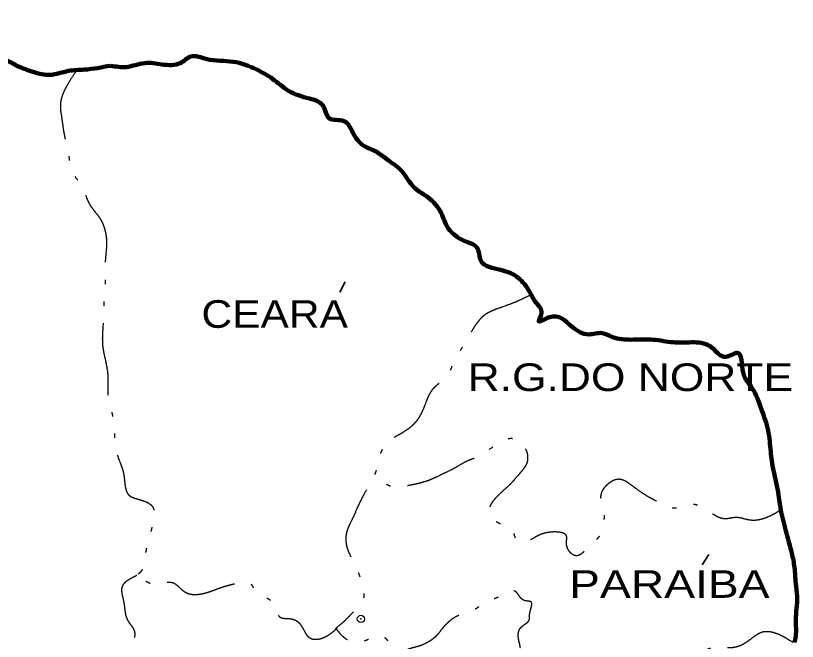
# Model space of a CAD drawing. Extents: x 512883 to 1063249, y 8784064 to 9081064.
# Drawn here: x 1001709 to 1034045, y 8999558 to 9025452 of the extents above; entities that cross this region are included whole.
import ezdxf

# ---------------------------------------------------------------- set-up
doc = ezdxf.new("R2010")
doc.units = 0
doc.header["$LTSCALE"] = 600
doc.header["$PDMODE"] = 32
doc.header["$PDSIZE"] = 300
doc.linetypes.add('DASH_DOUBLE_DOT', pattern=[9.2, 5, -1.2, 0.3, -1.2, 0.3, -1.2])
doc.layers.add('1', color=7, linetype='Continuous', lineweight=25)

msp = doc.modelspace()

# ---------------------------------------------------------------- linework, layer by layer
at = {"layer": '1', "lineweight": 35}
for p, q in [((1015118.6, 9014005.3), (1015336.7, 9014441.3)), ((1030108.9, 9002721.7), (1030381.5, 9003157.7))]:
    msp.add_line(p, q, dxfattribs=at)
at = {"layer": '1', "lineweight": 140}
for points in [[(996367.1, 9025452.4), (996476.1, 9025343.4), (997184.8, 9025234.4), (997784.4, 9024961.8), (998275, 9024852.8), (998056.9, 9024253.2), (998602, 9024144.2), (999365.2, 9023926.1), (1000400.9, 9023817.1), (1001218.5, 9023653.6), (1001763.6, 9023381), (1002472.3, 9023108.5), (1003126.4, 9022999.5), (1003889.5, 9023163), (1004543.7, 9023217.5), (1005633.9, 9023381)], [(1005633.9, 9023381), (1006288, 9023326.5), (1007051.1, 9023490), (1007759.8, 9023435.5), (1008522.9, 9023490), (1008959, 9023762.6), (1009613.1, 9023653.6), (1010703.3, 9023544.6), (1011684.5, 9023217.5), (1012338.6, 9022835.9), (1012992.7, 9022345.3), (1013864.9, 9022018.3), (1014410, 9021745.7), (1014682.6, 9021200.6), (1015282.2, 9021091.6), (1015663.7, 9020601), (1016045.3, 9020110.4), (1016590.4, 9019837.8), (1017135.5, 9019456.3), (1017626.1, 9019074.7), (1018225.7, 9018311.6), (1018770.8, 9017930), (1019315.9, 9017275.9), (1019588.5, 9016676.3), (1019970, 9016294.7), (1020406.1, 9016076.7), (1020787.7, 9015858.6), (1020951.2, 9015313.5), (1021768.9, 9014931.9), (1022423, 9014659.4), (1022913.6, 9014114.3), (1023240.7, 9013569.2), (1023458.7, 9013133.1), (1023349.7, 9012806), (1023785.8, 9012969.6), (1024712.4, 9012588), (1025421.1, 9012260.9), (1025966.2, 9012315.5), (1026402.2, 9012151.9), (1027165.4, 9012042.9), (1028092.1, 9012042.9), (1028909.7, 9011933.9), (1029672.8, 9011933.9), (1030436, 9011770.3), (1031090.1, 9011334.3), (1031580.7, 9011497.8), (1031798.8, 9010680.1), (1032180.3, 9010026), (1032561.9, 9009153.9), (1032834.4, 9008281.7), (1032943.5, 9007409.5), (1033052.5, 9006646.4), (1033270.5, 9005610.7), (1033379.5, 9004902.1), (1033597.6, 9004029.9), (1033815.6, 9003212.2), (1033924.6, 9002612.6), (1033979.2, 9001958.5), (1034033.7, 9001413.4), (1033979.2, 9000432.2), (1033979.2, 8999778.1), (1033924.6, 8999505.6)]]:
    msp.add_spline(points, degree=3, dxfattribs=at)
at = {"layer": '1', "linetype": 'DASH_DOUBLE_DOT'}
for points in [[(1004216.6, 9023163), (1003835, 9022563.4), (1003562.5, 9021800.2), (1003617, 9021200.6), (1003726, 9020492), (1003889.5, 9019783.3), (1004053.1, 9018965.7), (1004434.6, 9018420.6), (1004761.7, 9017657.5), (1005197.8, 9017057.8), (1005470.3, 9016076.7), (1005415.8, 9015259), (1005415.8, 9014441.3), (1005361.3, 9013841.7), (1005361.3, 9013242.1), (1005306.8, 9011824.9), (1005524.8, 9010516.6), (1005524.8, 9009753.5), (1005742.9, 9008772.3), (1005797.4, 9008063.7), (1005906.4, 9007300.5), (1006179, 9006482.9), (1006397, 9005610.7), (1006942.1, 9005392.7), (1007378.2, 9005120.1), (1007378.2, 9004411.5), (1007214.7, 9003757.3), (1007051.1, 9003048.7), (1006887.6, 9002449.1), (1006778.6, 9002340.1)], [(1023022.6, 9013896.2), (1022314, 9013569.2), (1021714.4, 9013351.1), (1021060.2, 9013024.1), (1020624.2, 9012479), (1020242.6, 9011824.9), (1019861, 9011170.7), (1019479.4, 9010462.1), (1018988.8, 9010026), (1018607.3, 9009262.9), (1018280.2, 9008663.3), (1017680.6, 9008172.7), (1017026.5, 9007736.6), (1016699.4, 9006973.5), (1016590.4, 9006537.4), (1016317.8, 9005992.3), (1015881.8, 9005174.6), (1015663.7, 9004684), (1015391.2, 9004029.9), (1015391.2, 9003539.3), (1015718.2, 9002776.2), (1016045.3, 9001904), (1016099.8, 9001358.9), (1015609.2, 9000704.8), (1015227.7, 9000323.2), (1014955.1, 9000105.2)], [(1033379.5, 9005011.1), (1032779.9, 9004684), (1032071.3, 9004575), (1031526.2, 9004684), (1031035.6, 9004629.5), (1030436, 9004902.1), (1029618.3, 9005229.1), (1028964.2, 9005065.6), (1028473.6, 9005229.1), (1027765, 9005610.7), (1027219.9, 9005992.3), (1026674.8, 9006264.8), (1026184.2, 9006046.8), (1025911.7, 9005610.7), (1026020.7, 9005011.1), (1026020.7, 9004411.5), (1025857.1, 9003920.9), (1025475.6, 9003539.3), (1024876, 9003103.2), (1024494.4, 9003593.8), (1024494.4, 9003920.9), (1023949.3, 9004084.4), (1023295.2, 9003920.9), (1022859.1, 9003702.8), (1022477.5, 9003702.8), (1022259.5, 9004138.9), (1022041.4, 9004302.5), (1021659.8, 9004466), (1021332.8, 9004847.6), (1022205, 9006101.3), (1022586.5, 9006537.4), (1022859.1, 9006918.9), (1022859.1, 9007409.5), (1022641, 9007736.6), (1022423, 9007900.1), (1021005.7, 9007300.5), (1020678.7, 9007137), (1020406.1, 9007028), (1019915.5, 9006755.4), (1019261.4, 9006428.3), (1018770.8, 9006210.3), (1017898.7, 9005992.3), (1017353.6, 9005937.8), (1016972, 9006101.3), (1016535.9, 9006537.4)], [(1006724.1, 9002285.6), (1006506, 9002176.6), (1006124.5, 9001849.5), (1006179, 9001195.4), (1006342.5, 9000432.2), (1006615, 8999996.2), (1006342.5, 8999178.5), (1005906.4, 8998687.9), (1005088.8, 8997924.8), (1004053.1, 8997270.6), (1003289.9, 8996889.1), (1003017.4, 8996289.5), (1002908.3, 8996180.4)], [(1015009.6, 9000105.2), (1014355.5, 8999669.1), (1013919.4, 8999669.1), (1013483.3, 9000268.7), (1013047.2, 9000486.7), (1012665.7, 9000541.2), (1012447.6, 9001031.8), (1012066.1, 9001358.9), (1011684.5, 9001576.9), (1011411.9, 9001958.5), (1010866.8, 9001958.5), (1010103.7, 9001740.5), (1009449.6, 9001522.4), (1008740.9, 9001576.9), (1008250.3, 9001958.5), (1007650.7, 9001958.5), (1007269.2, 9001958.5), (1006833.1, 9002340.1)], [(1033870.1, 8999505.6), (1033161.5, 8999887.1), (1032616.4, 8999941.6), (1032071.3, 8999614.6), (1031580.7, 8999342), (1031090.1, 8999287.5), (1030490.5, 8999287.5), (1029999.9, 8999015), (1029236.8, 8998633.4), (1028855.2, 8998415.3), (1028310.1, 8998415.3), (1027819.5, 8998687.9), (1027328.9, 8998851.4), (1026729.3, 8998578.9), (1026184.2, 8998960.5), (1025748.1, 8999015), (1025366.5, 8998578.9), (1025094, 8998197.3), (1024766.9, 8997706.7), (1024439.9, 8997107.1), (1024003.8, 8996671), (1023676.7, 8996507.5), (1023186.1, 8996562), (1022913.6, 8996780), (1022750.1, 8997161.6), (1022695.6, 8997706.7), (1022477.5, 8998033.8), (1021986.9, 8998088.3), (1021877.9, 8998415.3), (1022314, 8998796.9), (1022586.5, 8999233), (1022532, 8999560.1), (1022586.5, 9000105.2), (1022968.1, 9000486.7), (1022968.1, 9000650.3), (1023022.6, 9001195.4), (1022750.1, 9001249.9), (1022368.5, 9001631.5), (1021714.4, 9001413.4), (1021114.8, 9001140.9), (1020569.7, 9000813.8), (1020079.1, 9000650.3), (1019370.4, 9000105.2), (1019152.4, 8999832.6), (1018498.3, 8999396.5), (1017953.2, 8999233), (1017353.6, 8999124), (1017081, 8999614.6), (1016753.9, 8999778.1), (1016099.8, 8999560.1), (1015445.7, 8999614.6), (1014955.1, 9000105.2)]]:
    msp.add_spline(points, degree=3, dxfattribs=at)
at = {"layer": '1'}
msp.add_point((1015990.8, 9000486.7), dxfattribs=at)

# ---------------------------------------------------------------- texts
for s, width, p in [('CEARA', 1.15, (1009395.1, 9012533.5)), ('R.G.DO NORTE', 1.2, (1020406.1, 9009917)), ('PARAIBA', 1.25, (1024603.4, 9001358.9))]:
    msp.add_text(s, height=1144, dxfattribs=dict(at, width=width)).set_placement(p)

doc.saveas('drawing.dxf')
